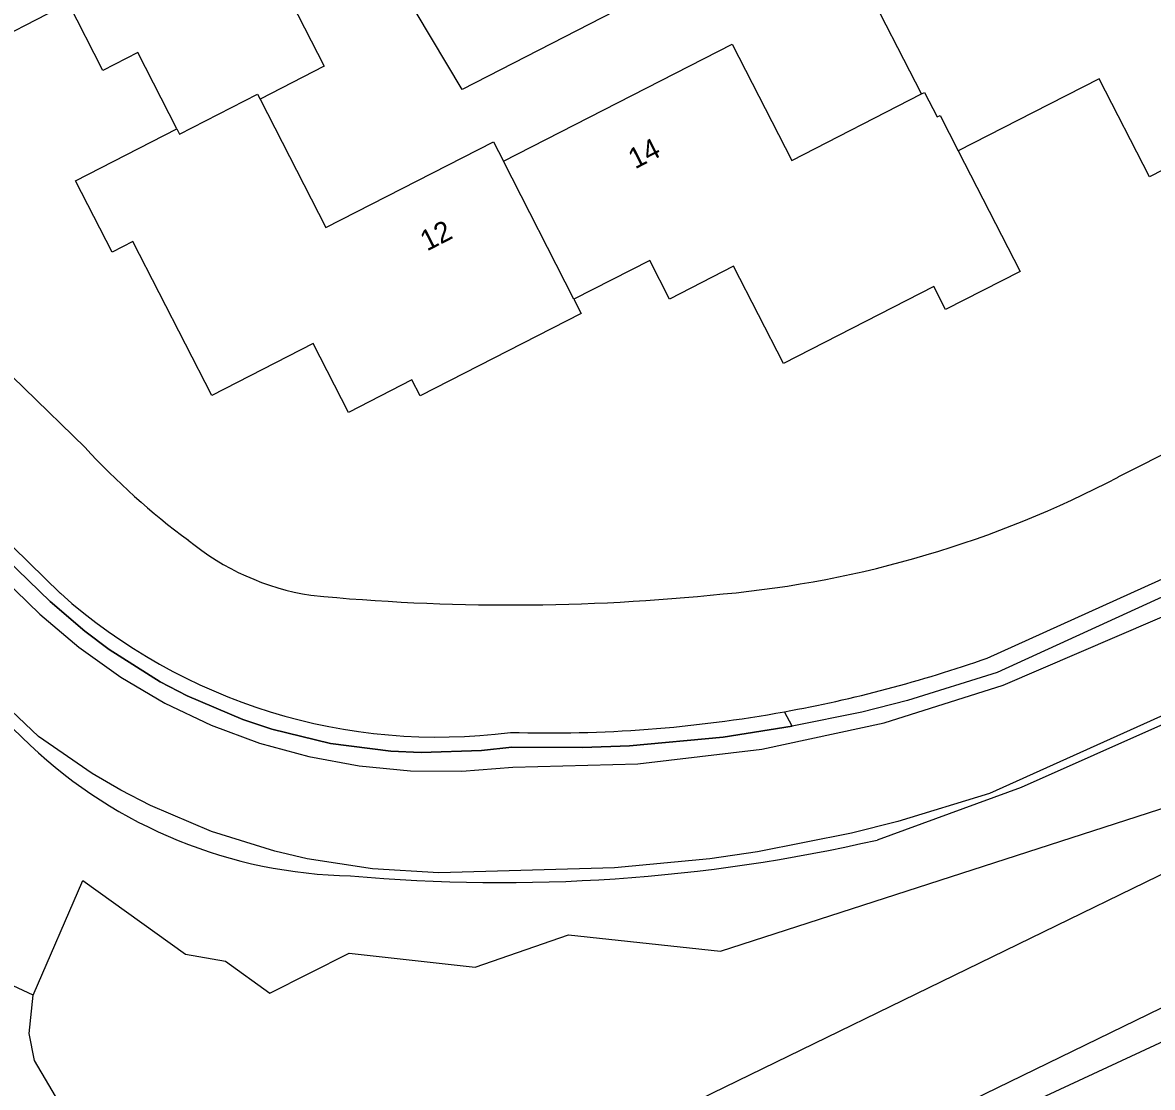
# Model space of a CAD drawing. Extents: x 162722 to 165099, y 384721 to 386283.
# Drawn here: x 163705.8 to 163760.7, y 384791.4 to 384843.2 of the extents above; entities that cross this region are included whole.
import ezdxf

# ---------------------------------------------------------------- set-up
doc = ezdxf.new("R2010")
doc.units = 0
for name, color, linetype in [('IMGEO_Berm_groen', 7, 'Continuous'), ('IMGEO_Erf', 7, 'Continuous'), ('IMGEO_Gemengd_bos', 7, 'Continuous'), ('IMGEO_Groenvoorziening', 7, 'Continuous'), ('IMGEO_Hek', 7, 'Continuous'), ('IMGEO_Moeras', 7, 'Continuous'), ('IMGEO_Pand', 7, 'Continuous'), ('IMGEO_Pand_nummerreeks', 7, 'Continuous'), ('IMGEO_Voetpad_open', 7, 'Continuous'), ('IMGEO_Waterloop', 7, 'Continuous')]:
    doc.layers.add(name, color=color, linetype=linetype)

msp = doc.modelspace()

# ---------------------------------------------------------------- linework, layer by layer
at = {"layer": 'IMGEO_Berm_groen'}
for points in [[(163706.139, 384808.003), (163680.683, 384832.479), (163678.197, 384835.444), (163678.562, 384835.713)], [(163772.044, 384814.309), (163752.813, 384805.661), (163748.356, 384804.289), (163746.095, 384803.718), (163741.521, 384802.81), (163739.213, 384802.475), (163734.57, 384802.042), (163726.021, 384801.8), (163722.798, 384801.981), (163719.609, 384802.479), (163718.038, 384802.846), (163714.958, 384803.812), (163711.989, 384805.077), (163710.555, 384805.819), (163709.16, 384806.63), (163706.545, 384808.42), (163682.557, 384831.217)], [(163782.254, 384797.588), (163778.727, 384801.101), (163777.866, 384802.318), (163771.742, 384813.691), (163754.362, 384805.941), (163747.346, 384803.391)], [(163763.146, 384794.457), (163716.594, 384772.834)]]:
    msp.add_lwpolyline(points, dxfattribs=at)
for centre, radius, start, end in [((163722.127, 384824.936), 23.288, 226.6435, 269.0231), ((163729.072, 384882.983), 81.663, 264.84145, 282.93039)]:
    msp.add_arc(centre, radius, start, end, dxfattribs=at)
at = {"layer": 'IMGEO_Erf'}
for points in [[(163708.809, 384822.485), (163699.897, 384831.148), (163688.409, 384842.314)], [(163777.48, 384830.304), (163759.065, 384821.045)]]:
    msp.add_lwpolyline(points, dxfattribs=at)
for centre, radius, start, end in [((163735.137, 384846.784), 35.827, 222.7051, 233.5161), ((163735.137, 384866.647), 51.499, 275.2569, 297.6869), ((163721.732, 384827.589), 12.44, 230.5888, 261.07), ((163729.505, 384914.922), 100.094, 264.43638, 275.93504)]:
    msp.add_arc(centre, radius, start, end, dxfattribs=at)
at = {"layer": 'IMGEO_Gemengd_bos'}
for points in [[(163694.511, 384828.206), (163707.608, 384815.394)], [(163693.84, 384827.84), (163707.119, 384814.998), (163708.798, 384813.547), (163709.977, 384812.661), (163712.47, 384811.086), (163713.777, 384810.402), (163716.492, 384809.252), (163717.893, 384808.789), (163720.759, 384808.094), (163723.683, 384807.713), (163725.156, 384807.642), (163728.104, 384807.74), (163729.569, 384807.909), (163733.004, 384807.892), (163735.291, 384807.981), (163739.848, 384808.398), (163743.207, 384808.923)], [(163743.207, 384808.923), (163742.838, 384809.633)]]:
    msp.add_lwpolyline(points, dxfattribs=at)
for centre, radius, start, end in [((163725.978, 384836.026), 27.625, 228.3184, 277.3383), ((163731.355, 384872.971), 64.37, 268.35499, 280.2761)]:
    msp.add_arc(centre, radius, start, end, dxfattribs=at)
at = {"layer": 'IMGEO_Groenvoorziening'}
for points in [[(163682.411, 384837.903), (163706.609, 384814.386), (163708.509, 384812.767), (163710.543, 384811.319), (163712.696, 384810.054), (163714.951, 384808.982), (163717.291, 384808.111), (163719.698, 384807.447), (163722.153, 384806.996), (163724.639, 384806.761), (163727.135, 384806.743), (163729.624, 384806.943), (163735.703, 384807.091), (163741.741, 384807.81), (163747.685, 384809.094), (163753.482, 384810.931), (163770.227, 384818.134)], [(163752.704, 384812.241), (163775.21, 384822.428), (163775.549, 384821.775)], [(163775.549, 384821.775), (163753.19, 384811.537), (163748.82, 384810.18), (163746.601, 384809.617), (163743.207, 384808.923)]]:
    msp.add_lwpolyline(points, dxfattribs=at)
msp.add_arc((163731.312, 384873.2), 64.603, 280.27699, 289.33701, dxfattribs=at)
at = {"layer": 'IMGEO_Hek'}
for points in [[(163772.044, 384814.309), (163752.813, 384805.661), (163748.356, 384804.289), (163746.095, 384803.718), (163741.521, 384802.81), (163739.213, 384802.475), (163734.57, 384802.042), (163726.021, 384801.8), (163722.798, 384801.981), (163719.609, 384802.479), (163718.038, 384802.846), (163714.958, 384803.812), (163711.989, 384805.077), (163710.555, 384805.819), (163709.16, 384806.63), (163706.545, 384808.42), (163682.557, 384831.217)], [(163743.207, 384808.923), (163739.848, 384808.398), (163735.291, 384807.981), (163733.004, 384807.892), (163729.569, 384807.909), (163728.104, 384807.74), (163725.156, 384807.642), (163723.683, 384807.713), (163720.759, 384808.094), (163717.893, 384808.789), (163716.492, 384809.252), (163713.777, 384810.402), (163712.47, 384811.086), (163709.977, 384812.661), (163708.798, 384813.547), (163707.119, 384814.998), (163693.84, 384827.84)], [(163775.549, 384821.775), (163753.19, 384811.537), (163748.82, 384810.18), (163746.601, 384809.617), (163743.207, 384808.923)]]:
    msp.add_lwpolyline(points, dxfattribs=at)
at = {"layer": 'IMGEO_Moeras'}
msp.add_lwpolyline([(163706.284, 384795.844), (163708.701, 384801.415), (163713.692, 384797.843), (163715.648, 384797.501), (163717.801, 384795.935), (163721.666, 384797.892), (163727.782, 384797.207), (163732.331, 384798.773), (163739.719, 384797.99), (163763.202, 384805.573), (163764.572, 384806.65), (163764.328, 384808.753), (163770.688, 384811.933), (163774.325, 384804.43)], dxfattribs=at)
at = {"layer": 'IMGEO_Pand'}
for points in [[(163705.313, 384856.295), (163708.601, 384849.88), (163714.389, 384852.846), (163720.439, 384841.041), (163717.322, 384839.444)], [(163713.273, 384837.99), (163711.371, 384841.703), (163709.682, 384840.837), (163708.008, 384844.104), (163703.261, 384841.671), (163699.491, 384849.029), (163698.271, 384848.404), (163696.535, 384851.79), (163698.425, 384852.759)], [(163749.509, 384839.691), (163746.634, 384845.301), (163758.231, 384851.244), (163761.125, 384845.596), (163767.436, 384848.831)], [(163729.169, 384836.424), (163740.286, 384842.121), (163743.191, 384836.453), (163749.509, 384839.691)], [(163770.146, 384835.223), (163768.472, 384838.488), (163767.984, 384839.44), (163760.593, 384835.653), (163758.142, 384840.435), (163754.931, 384838.79), (163751.296, 384836.928)], [(163713.273, 384837.99), (163713.401, 384837.744), (163717.196, 384839.688), (163717.322, 384839.444)], [(163717.322, 384839.444), (163720.527, 384833.19), (163728.684, 384837.37), (163729.169, 384836.424)], [(163749.509, 384839.691), (163749.653, 384839.763), (163750.262, 384838.574), (163750.412, 384838.652), (163751.296, 384836.928)], [(163732.597, 384829.704), (163732.949, 384829.011), (163725.116, 384824.997), (163724.714, 384825.782), (163721.623, 384824.198), (163719.908, 384827.545), (163714.977, 384825.019), (163711.134, 384832.518), (163710.123, 384832), (163708.347, 384835.465), (163713.273, 384837.99)], [(163751.296, 384836.928), (163754.302, 384831.061), (163750.675, 384829.203), (163750.103, 384830.319), (163742.791, 384826.571), (163740.362, 384831.311), (163737.243, 384829.712), (163736.28, 384831.592), (163732.597, 384829.704)], [(163732.597, 384829.704), (163729.169, 384836.424)]]:
    msp.add_lwpolyline(points, dxfattribs=at)
at = {"layer": 'IMGEO_Voetpad_open'}
msp.add_lwpolyline([(163738.311, 384845.645), (163727.158, 384839.91), (163724.179, 384844.915), (163714.216, 384857.037)], dxfattribs=at)
at = {"layer": 'IMGEO_Waterloop'}
for points in [[(163774.325, 384804.43), (163772.845, 384804.876), (163771.045, 384805.122), (163769.123, 384805.067), (163767.868, 384804.834), (163766.557, 384804.434), (163765.56, 384804), (163764.116, 384803.138), (163716.951, 384780.172), (163716.579, 384780.173), (163715.236, 384780.396), (163714.231, 384780.809), (163713.024, 384781.694), (163712.205, 384782.713), (163706.351, 384792.662), (163706.085, 384793.978), (163706.284, 384795.844)], [(163706.284, 384795.844), (163703.631, 384797.077), (163703.109, 384796.766)], [(163716.445, 384773.436), (163763.61, 384796.402)]]:
    msp.add_lwpolyline(points, dxfattribs=at)

# ---------------------------------------------------------------- texts
at = {"layer": 'IMGEO_Pand_nummerreeks'}
for s, rotation, p in [('14', 27.1333, (163735.569, 384836.019)), ('12', 27.1354, (163725.444, 384832.024))]:
    msp.add_text(s, height=1, rotation=rotation, dxfattribs=at).set_placement(p)

doc.saveas('drawing.dxf')
